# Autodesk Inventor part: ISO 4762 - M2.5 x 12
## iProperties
Created: 2008-01
Part Number: ISO 4762 - M2.5 x 12
Material: Stainless Steel, 440C
Description: Hexagon Socket Head Cap Screw
Document SubType Name: Modeling
Standard: ISO 4762
Designer: latalom
Standard Revision: Fourth edition 2004-03-01
Standards Organization: ISO
Language: en-US
Size Designation: M2.5 x 12
Categories: <MemberInstance><Categories><Category DisplayName="Fasteners" InternalName="e4da775c-781d-43d5-af7c-5136215cf5a6" Mnemonic="FSTN"><Category DisplayName="Bolts"
Density: 7.75 g/cm^3
IsCustomPart: 0
Author: latalom
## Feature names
1. Body [Revolution]
2. Slot [Extrusion]
3. Fillet1
4. Chamfer1
5. Fillet2
